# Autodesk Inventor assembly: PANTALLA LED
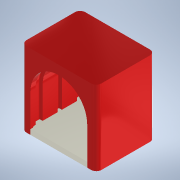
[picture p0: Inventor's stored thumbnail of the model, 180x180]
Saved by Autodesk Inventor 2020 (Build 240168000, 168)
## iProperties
Created: 2022-09
Part Number: PANTALLA LED
Document SubType Name: Assembly
Designer: SEBAS
Author: SEBAS
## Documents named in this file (4)
- D:\TRABAJO UNIVERSIDAD\MOLDE LATERAL EXTENDIDO\PANTALLA LED\PANTALLA LED.iam
- D:\TRABAJO UNIVERSIDAD\MOLDE LATERAL EXTENDIDO\MOLDE LATERAL\MOLDE LATERAL.ipt
- D:\TRABAJO UNIVERSIDAD\MOLDE LATERAL EXTENDIDO\TAPA\TAPA.ipt
- D:\TRABAJO UNIVERSIDAD\MOLDE LATERAL EXTENDIDO\LENTE\LENTE.ipt
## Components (3 placed, 3 different names)
1. MOLDE LATERAL:1 — Nivelación:1, Nivelación:2, Nivelación:3, Nivelación:4, Coincidencia:1, Nivelación:5, Coincidencia:2
2. LENTE:1 — Coincidencia:2, Coincidencia:3
3. TAPA:1 — Nivelación:4, Coincidencia:1, Nivelación:5, Coincidencia:3
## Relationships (8: Flush 5, Mate 3)
- Nivelación:1 [Flush]: MOLDE LATERAL:1
- Nivelación:2 [Flush]: MOLDE LATERAL:1
- Nivelación:3 [Flush]: MOLDE LATERAL:1
- Nivelación:4 [Flush]: MOLDE LATERAL:1 ↔ TAPA:1
- Coincidencia:1 [Mate]: MOLDE LATERAL:1 ↔ TAPA:1
- Nivelación:5 [Flush]: MOLDE LATERAL:1 ↔ TAPA:1
- Coincidencia:2 [Mate]: MOLDE LATERAL:1 ↔ LENTE:1
- Coincidencia:3 [Mate]: LENTE:1 ↔ TAPA:1
